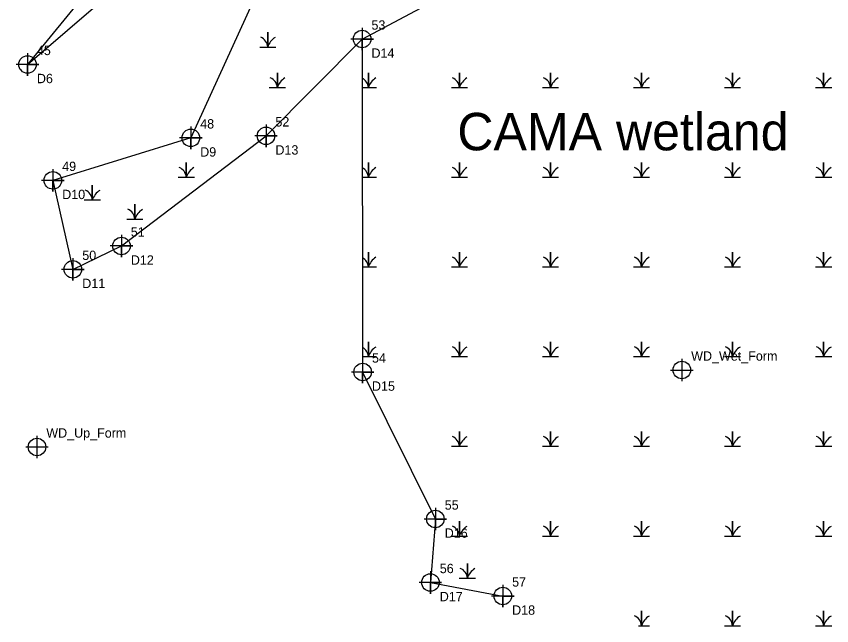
# Model space of a CAD drawing. Extents: x 2678633 to 2679425, y 623836 to 624637.
# Drawn here: x 2678911.2 to 2679128.9, y 623859.6 to 624022.3 of the extents above; entities that cross this region are included whole.
import ezdxf

# ---------------------------------------------------------------- set-up
doc = ezdxf.new("R2010")
doc.units = 0
for name, color, linetype in [('Cogo Default Point CELL', 7, 'Continuous'), ('COGO Default Point Number', 7, 'Continuous'), ('Default', 7, 'Continuous'), ('Exist Environmental Wetland Boundary', 7, 'Continuous'), ('Exist Environmental Wetland Boundary Cogo Comment', 7, 'Continuous'), ('Exist Environmental Wetland Boundary Cogo Number', 7, 'Continuous'), ('Exist Environmental Wetland Boundary Cogo Point CELL', 7, 'Continuous'), ('Exist Environmental Wetland Boundary Text', 7, 'Continuous'), ('Exist Hydro Swamp or Marsh', 7, 'Continuous')]:
    doc.layers.add(name, color=color, linetype=linetype)

msp = doc.modelspace()

# ---------------------------------------------------------------- linework, layer by layer
at = {"layer": 'Cogo Default Point CELL'}
for points in [[(2679088.92, 623930.88), (2679088.92, 623927.88)], [(2679085.92, 623927.88), (2679088.92, 623927.88)], [(2679088.92, 623927.88), (2679091.92, 623927.88)], [(2679088.92, 623927.88), (2679088.92, 623924.88)], [(2678916.72, 623910.33), (2678916.72, 623907.33)], [(2678913.72, 623907.33), (2678916.72, 623907.33)], [(2678916.72, 623907.33), (2678919.72, 623907.33)], [(2678916.72, 623907.33), (2678916.72, 623904.33)]]:
    msp.add_lwpolyline(points, dxfattribs=at)
for centre in [(2679088.92, 623927.88), (2678916.72, 623907.33)]:
    msp.add_circle(centre, 2.34, dxfattribs=at)
at = {"layer": 'Exist Environmental Wetland Boundary'}
for points in [[(2678974.4, 624082.96), (2678914.21, 624009.47), (2678966.95, 624054.85), (2678977.91, 624034.05), (2678957.81, 623989.86), (2678920.96, 623978.51), (2678926.32, 623954.76), (2678939.29, 623961), (2678977.9, 623990.4), (2679003.55, 624016.25)], [(2679003.55, 624016.25), (2679026.31, 624028.4), (2679034.63, 624059.59), (2679038.27, 624083.52)], [(2679003.55, 624016.25), (2679003.68, 623927.34), (2679023.11, 623888.09), (2679021.79, 623871.14), (2679041.11, 623867.53)]]:
    msp.add_lwpolyline(points, dxfattribs=at)
at = {"layer": 'Exist Environmental Wetland Boundary Cogo Point CELL'}
for points in [[(2679003.55, 624019.25), (2679003.55, 624013.25), (2679003.55, 624016.25), (2679006.55, 624016.25), (2679000.55, 624016.25)], [(2678914.21, 624012.47), (2678914.21, 624006.47), (2678914.21, 624009.47), (2678917.21, 624009.47), (2678911.21, 624009.47)], [(2678977.9, 623993.4), (2678977.9, 623987.4), (2678977.9, 623990.4), (2678980.9, 623990.4), (2678974.9, 623990.4)], [(2678957.81, 623992.86), (2678957.81, 623986.86), (2678957.81, 623989.86), (2678960.81, 623989.86), (2678954.81, 623989.86)], [(2678920.96, 623981.51), (2678920.96, 623975.51), (2678920.96, 623978.51), (2678923.96, 623978.51), (2678917.96, 623978.51)], [(2678939.29, 623964), (2678939.29, 623958), (2678939.29, 623961), (2678942.29, 623961), (2678936.29, 623961)], [(2678926.32, 623957.76), (2678926.32, 623951.76), (2678926.32, 623954.76), (2678929.32, 623954.76), (2678923.32, 623954.76)], [(2679003.68, 623930.34), (2679003.68, 623924.34), (2679003.68, 623927.34), (2679006.68, 623927.34), (2679000.68, 623927.34)], [(2679023.11, 623891.09), (2679023.11, 623885.09), (2679023.11, 623888.09), (2679026.11, 623888.09), (2679020.11, 623888.09)], [(2679021.79, 623874.14), (2679021.79, 623868.14), (2679021.79, 623871.14), (2679024.79, 623871.14), (2679018.79, 623871.14)], [(2679041.11, 623870.53), (2679041.11, 623864.53), (2679041.11, 623867.53), (2679044.11, 623867.53), (2679038.11, 623867.53)]]:
    msp.add_lwpolyline(points, dxfattribs=at)
for centre in [(2679003.55, 624016.25), (2678914.21, 624009.47), (2678957.81, 623989.86), (2678977.9, 623990.4), (2678920.96, 623978.51), (2678939.29, 623961), (2678926.32, 623954.76), (2679003.68, 623927.34), (2679023.11, 623888.09), (2679021.79, 623871.14), (2679041.11, 623867.53)]:
    msp.add_circle(centre, 2.34, dxfattribs=at)
at = {"layer": 'Exist Hydro Swamp or Marsh'}
for p, q in [((2678978.35, 624015.91), (2678978.35, 624015.91)), ((2678931.51, 623975.08), (2678931.51, 623975.08)), ((2678942.87, 623969.98), (2678942.87, 623969.98)), ((2679031.66, 623874.09), (2679031.66, 623874.09))]:
    msp.add_line(p, q, dxfattribs=at)
for points in [[(2678976.2, 624014.13), (2678978.35, 624014.13), (2678978.35, 624018.07), (2678978.35, 624014.13), (2678980.5, 624014.13)], [(2678978.77, 624003.31), (2678980.92, 624003.31), (2678980.92, 624007.26), (2678980.92, 624003.31), (2678983.07, 624003.31)], [(2679003.57, 624003.31), (2679005.23, 624003.31), (2679005.23, 624007.26), (2679005.23, 624003.31), (2679007.38, 624003.31)], [(2679027.39, 624003.31), (2679029.54, 624003.31), (2679029.54, 624007.26), (2679029.54, 624003.31), (2679031.69, 624003.31)], [(2679051.7, 624003.31), (2679053.86, 624003.31), (2679053.86, 624007.26), (2679053.86, 624003.31), (2679056.01, 624003.31)], [(2679076.02, 624003.31), (2679078.17, 624003.31), (2679078.17, 624007.26), (2679078.17, 624003.31), (2679080.32, 624003.31)], [(2679100.33, 624003.31), (2679102.48, 624003.31), (2679102.48, 624007.26), (2679102.48, 624003.31), (2679104.63, 624003.31)], [(2679124.64, 624003.31), (2679126.79, 624003.31), (2679126.79, 624007.26), (2679126.79, 624003.31), (2679128.94, 624003.31)], [(2678954.45, 623979.36), (2678956.61, 623979.36), (2678956.61, 623983.31), (2678956.61, 623979.36), (2678958.76, 623979.36)], [(2679003.61, 623979.36), (2679005.23, 623979.36), (2679005.23, 623983.31), (2679005.23, 623979.36), (2679007.38, 623979.36)], [(2679027.39, 623979.36), (2679029.54, 623979.36), (2679029.54, 623983.31), (2679029.54, 623979.36), (2679031.69, 623979.36)], [(2679051.7, 623979.36), (2679053.86, 623979.36), (2679053.86, 623983.31), (2679053.86, 623979.36), (2679056.01, 623979.36)], [(2679076.02, 623979.36), (2679078.17, 623979.36), (2679078.17, 623983.31), (2679078.17, 623979.36), (2679080.32, 623979.36)], [(2679100.33, 623979.36), (2679102.48, 623979.36), (2679102.48, 623983.31), (2679102.48, 623979.36), (2679104.63, 623979.36)], [(2679124.64, 623979.36), (2679126.79, 623979.36), (2679126.79, 623983.31), (2679126.79, 623979.36), (2679128.94, 623979.36)], [(2678929.36, 623973.3), (2678931.51, 623973.3), (2678931.51, 623977.24), (2678931.51, 623973.3), (2678933.66, 623973.3)], [(2678940.72, 623968.19), (2678942.88, 623968.19), (2678942.88, 623972.14), (2678942.88, 623968.19), (2678945.03, 623968.19)], [(2679003.64, 623955.41), (2679005.23, 623955.41), (2679005.23, 623959.36), (2679005.23, 623955.41), (2679007.38, 623955.41)], [(2679027.39, 623955.41), (2679029.54, 623955.41), (2679029.54, 623959.36), (2679029.54, 623955.41), (2679031.69, 623955.41)], [(2679051.7, 623955.41), (2679053.86, 623955.41), (2679053.86, 623959.36), (2679053.86, 623955.41), (2679056.01, 623955.41)], [(2679076.02, 623955.41), (2679078.17, 623955.41), (2679078.17, 623959.36), (2679078.17, 623955.41), (2679080.32, 623955.41)], [(2679100.33, 623955.41), (2679102.48, 623955.41), (2679102.48, 623959.36), (2679102.48, 623955.41), (2679104.63, 623955.41)], [(2679124.64, 623955.41), (2679126.79, 623955.41), (2679126.79, 623959.36), (2679126.79, 623955.41), (2679128.94, 623955.41)], [(2679003.68, 623931.46), (2679005.23, 623931.46), (2679005.23, 623935.41), (2679005.23, 623931.46), (2679007.38, 623931.46)], [(2679027.39, 623931.46), (2679029.54, 623931.46), (2679029.54, 623935.41), (2679029.54, 623931.46), (2679031.69, 623931.46)], [(2679051.7, 623931.46), (2679053.86, 623931.46), (2679053.86, 623935.41), (2679053.86, 623931.46), (2679056.01, 623931.46)], [(2679076.02, 623931.46), (2679078.17, 623931.46), (2679078.17, 623935.41), (2679078.17, 623931.46), (2679080.32, 623931.46)], [(2679100.33, 623931.46), (2679102.48, 623931.46), (2679102.48, 623935.41), (2679102.48, 623931.46), (2679104.63, 623931.46)], [(2679124.64, 623931.46), (2679126.79, 623931.46), (2679126.79, 623935.41), (2679126.79, 623931.46), (2679128.94, 623931.46)], [(2679027.39, 623907.51), (2679029.54, 623907.51), (2679029.54, 623911.46), (2679029.54, 623907.51), (2679031.69, 623907.51)], [(2679051.7, 623907.51), (2679053.86, 623907.51), (2679053.86, 623911.46), (2679053.86, 623907.51), (2679056.01, 623907.51)], [(2679076.02, 623907.51), (2679078.17, 623907.51), (2679078.17, 623911.46), (2679078.17, 623907.51), (2679080.32, 623907.51)], [(2679100.33, 623907.51), (2679102.48, 623907.51), (2679102.48, 623911.46), (2679102.48, 623907.51), (2679104.63, 623907.51)], [(2679124.64, 623907.51), (2679126.79, 623907.51), (2679126.79, 623911.46), (2679126.79, 623907.51), (2679128.94, 623907.51)], [(2679027.39, 623883.56), (2679029.54, 623883.56), (2679029.54, 623887.51), (2679029.54, 623883.56), (2679031.69, 623883.56)], [(2679051.7, 623883.56), (2679053.86, 623883.56), (2679053.86, 623887.51), (2679053.86, 623883.56), (2679056.01, 623883.56)], [(2679076.02, 623883.56), (2679078.17, 623883.56), (2679078.17, 623887.51), (2679078.17, 623883.56), (2679080.32, 623883.56)], [(2679100.33, 623883.56), (2679102.48, 623883.56), (2679102.48, 623887.51), (2679102.48, 623883.56), (2679104.63, 623883.56)], [(2679124.64, 623883.56), (2679126.79, 623883.56), (2679126.79, 623887.51), (2679126.79, 623883.56), (2679128.94, 623883.56)], [(2679029.51, 623872.31), (2679031.66, 623872.31), (2679031.66, 623876.26), (2679031.66, 623872.31), (2679033.81, 623872.31)], [(2679077.39, 623859.61), (2679078.17, 623859.61), (2679078.17, 623863.56), (2679078.17, 623859.61), (2679080.32, 623859.61)], [(2679100.33, 623859.61), (2679102.48, 623859.61), (2679102.48, 623863.56), (2679102.48, 623859.61), (2679104.63, 623859.61)], [(2679124.64, 623859.61), (2679126.79, 623859.61), (2679126.79, 623863.56), (2679126.79, 623859.61), (2679128.94, 623859.61)]]:
    msp.add_lwpolyline(points, dxfattribs=at)
for centre, radius, start, end in [((2678975.29, 624013.91), 3.07, 4.1403, 67.535), ((2678982.91, 624012.61), 4.81, 122.1274, 161.6222), ((2678977.85, 624003.09), 3.07, 4.1403, 67.535), ((2678985.48, 624001.8), 4.81, 122.1274, 161.6222), ((2679002.16, 624003.09), 3.07, 4.1403, 62.8726), ((2679009.79, 624001.8), 4.81, 122.1274, 161.6222), ((2679026.48, 624003.09), 3.07, 4.1403, 67.535), ((2679034.1, 624001.8), 4.81, 122.1274, 161.6222), ((2679050.79, 624003.09), 3.07, 4.1403, 67.535), ((2679058.42, 624001.8), 4.81, 122.1274, 161.6222), ((2679075.1, 624003.09), 3.07, 4.1403, 67.535), ((2679082.73, 624001.8), 4.81, 122.1274, 161.6222), ((2679099.41, 624003.09), 3.07, 4.1403, 67.535), ((2679107.04, 624001.8), 4.81, 122.1274, 161.6222), ((2679123.73, 624003.09), 3.07, 4.1403, 67.535), ((2679131.35, 624001.8), 4.81, 122.1274, 161.6222), ((2678953.54, 623979.14), 3.07, 4.1403, 67.535), ((2678961.17, 623977.85), 4.81, 122.1274, 161.6222), ((2679002.16, 623979.14), 3.07, 4.1403, 62.1136), ((2679009.79, 623977.85), 4.81, 122.1274, 161.6222), ((2679026.48, 623979.14), 3.07, 4.1403, 67.535), ((2679034.1, 623977.85), 4.81, 122.1274, 161.6222), ((2679050.79, 623979.14), 3.07, 4.1403, 67.535), ((2679058.42, 623977.85), 4.81, 122.1274, 161.6222), ((2679075.1, 623979.14), 3.07, 4.1403, 67.535), ((2679082.73, 623977.85), 4.81, 122.1274, 161.6222), ((2679099.41, 623979.14), 3.07, 4.1403, 67.535), ((2679107.04, 623977.85), 4.81, 122.1274, 161.6222), ((2679123.73, 623979.14), 3.07, 4.1403, 67.535), ((2679131.35, 623977.85), 4.81, 122.1274, 161.6222), ((2678928.45, 623973.08), 3.07, 4.1403, 67.535), ((2678936.07, 623971.78), 4.81, 122.1274, 161.6222), ((2678939.81, 623967.97), 3.07, 4.1403, 67.535), ((2678947.44, 623966.68), 4.81, 122.1274, 161.6222), ((2679002.16, 623955.19), 3.07, 4.1403, 61.3492), ((2679009.79, 623953.9), 4.81, 122.1274, 161.6222), ((2679026.48, 623955.19), 3.07, 4.1403, 67.535), ((2679034.1, 623953.9), 4.81, 122.1274, 161.6222), ((2679050.79, 623955.19), 3.07, 4.1403, 67.535), ((2679058.42, 623953.9), 4.81, 122.1274, 161.6222), ((2679075.1, 623955.19), 3.07, 4.1403, 67.535), ((2679082.73, 623953.9), 4.81, 122.1274, 161.6222), ((2679099.41, 623955.19), 3.07, 4.1403, 67.535), ((2679107.04, 623953.9), 4.81, 122.1274, 161.6222), ((2679123.73, 623955.19), 3.07, 4.1403, 67.535), ((2679131.35, 623953.9), 4.81, 122.1274, 161.6222), ((2679002.16, 623931.24), 3.07, 4.1403, 60.5792), ((2679009.79, 623929.95), 4.81, 122.1274, 161.6222), ((2679026.48, 623931.24), 3.07, 4.1403, 67.535), ((2679034.1, 623929.95), 4.81, 122.1274, 161.6222), ((2679050.79, 623931.24), 3.07, 4.1403, 67.535), ((2679058.42, 623929.95), 4.81, 122.1274, 161.6222), ((2679075.1, 623931.24), 3.07, 4.1403, 67.535), ((2679082.73, 623929.95), 4.81, 122.1274, 161.6222), ((2679099.41, 623931.24), 3.07, 4.1403, 67.535), ((2679107.04, 623929.95), 4.81, 122.1274, 161.6222), ((2679123.73, 623931.24), 3.07, 4.1403, 67.535), ((2679131.35, 623929.95), 4.81, 122.1274, 161.6222), ((2679026.48, 623907.29), 3.07, 4.1403, 67.535), ((2679034.1, 623906), 4.81, 122.1274, 161.6222), ((2679050.79, 623907.29), 3.07, 4.1403, 67.535), ((2679058.42, 623906), 4.81, 122.1274, 161.6222), ((2679075.1, 623907.29), 3.07, 4.1403, 67.535), ((2679082.73, 623906), 4.81, 122.1274, 161.6222), ((2679099.41, 623907.29), 3.07, 4.1403, 67.535), ((2679107.04, 623906), 4.81, 122.1274, 161.6222), ((2679123.73, 623907.29), 3.07, 4.1403, 67.535), ((2679131.35, 623906), 4.81, 122.1274, 161.6222), ((2679026.48, 623883.34), 3.07, 4.1403, 67.535), ((2679034.1, 623882.05), 4.81, 122.1274, 161.6222), ((2679050.79, 623883.34), 3.07, 4.1403, 67.535), ((2679058.42, 623882.05), 4.81, 122.1274, 161.6222), ((2679075.1, 623883.34), 3.07, 4.1403, 67.535), ((2679082.73, 623882.05), 4.81, 122.1274, 161.6222), ((2679099.41, 623883.34), 3.07, 4.1403, 67.535), ((2679107.04, 623882.05), 4.81, 122.1274, 161.6222), ((2679123.73, 623883.34), 3.07, 4.1403, 67.535), ((2679131.35, 623882.05), 4.81, 122.1274, 161.6222), ((2679028.6, 623872.09), 3.07, 4.1403, 67.535), ((2679036.22, 623870.8), 4.81, 122.1274, 161.6222), ((2679075.1, 623859.39), 3.07, 4.1403, 67.535), ((2679082.73, 623858.1), 4.81, 122.1274, 161.6222), ((2679099.41, 623859.39), 3.07, 4.1403, 67.535), ((2679107.04, 623858.1), 4.81, 122.1274, 161.6222), ((2679123.73, 623859.39), 3.07, 4.1403, 67.535), ((2679131.35, 623858.1), 4.81, 122.1274, 161.6222)]:
    msp.add_arc(centre, radius, start, end, dxfattribs=at)

# ---------------------------------------------------------------- texts
at = {"layer": 'COGO Default Point Number'}
msp.add_text('WD_Wet_Form', height=2.5, dxfattribs=at).set_placement((2679091.42, 623930.38))
at = {"layer": 'Default'}
msp.add_text('WD_Up_Form', height=2.5, dxfattribs=at).set_placement((2678919.22, 623909.83))
at = {"layer": 'Exist Environmental Wetland Boundary Cogo Comment'}
for s, p in [('D14', (2679006.05, 624011.25)), ('D6', (2678916.71, 624004.47)), ('D9', (2678960.31, 623984.86)), ('D13', (2678980.4, 623985.4)), ('D10', (2678923.46, 623973.51)), ('D12', (2678941.79, 623956)), ('D11', (2678928.82, 623949.76)), ('D15', (2679006.18, 623922.34)), ('D16', (2679025.61, 623883.09)), ('D17', (2679024.29, 623866.14)), ('D18', (2679043.61, 623862.54))]:
    msp.add_text(s, height=2.5, dxfattribs=at).set_placement(p)
at = {"layer": 'Exist Environmental Wetland Boundary Cogo Number'}
for s, p in [('53', (2679006.05, 624018.75)), ('45', (2678916.71, 624011.97)), ('52', (2678980.4, 623992.9)), ('48', (2678960.31, 623992.36)), ('49', (2678923.46, 623981.01)), ('51', (2678941.79, 623963.5)), ('50', (2678928.82, 623957.26)), ('54', (2679006.18, 623929.84)), ('55', (2679025.61, 623890.59)), ('56', (2679024.29, 623873.64)), ('57', (2679043.61, 623870.04))]:
    msp.add_text(s, height=2.5, dxfattribs=at).set_placement(p)
at = {"layer": 'Exist Environmental Wetland Boundary Text'}
msp.add_text('CAMA wetland', height=10, dxfattribs=at).set_placement((2679028.98, 623986.54))

doc.saveas('drawing.dxf')
